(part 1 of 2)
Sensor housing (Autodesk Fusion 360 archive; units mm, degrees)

design "Attacco Sensori Def 4" references "Connettore Sensori"
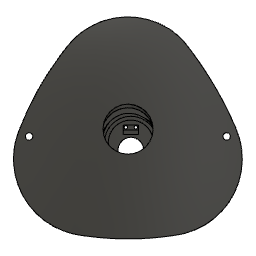
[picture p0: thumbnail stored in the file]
component_insert "Inserimento componente"
work_plane "Piano di lavoro1" AlongDistance 0
sketch "Schizzo1" plane through (0, 0, -8) normal (0, 0, 1) x axis (-1, 0, 0)
  line L1 (7.8557, -0.25) -> (4.1443, -6.6782)
  line L2 (4.1443, 6.6782) -> (7.8557, 0.25)
  line L3 (-3.7113, 6.9282) -> (3.7113, 6.9282)
  line L4 (-7.8557, 0.25) -> (-4.1443, 6.6782)
  line L5 (-4.1443, -6.6782) -> (-7.8557, -0.25)
  line L6 (3.7113, -6.9282) -> (-3.7113, -6.9282)
  curve K1
  circle C1 centre (0, 0) radius 5.5
  arc A1 centre (3.7113, -6.4282) radius 0.5 clockwise from (4.1443, -6.6782) to (3.7113, -6.9282)
  arc A2 centre (7.4226, 0) radius 0.5 clockwise from (7.8557, 0.25) to (7.8557, -0.25)
  arc A3 centre (3.7113, 6.4282) radius 0.5 clockwise from (3.7113, 6.9282) to (4.1443, 6.6782)
  arc A4 centre (-3.7113, 6.4282) radius 0.5 clockwise from (-4.1443, 6.6782) to (-3.7113, 6.9282)
  arc A5 centre (-7.4226, 0) radius 0.5 clockwise from (-7.8557, -0.25) to (-7.8557, 0.25)
  arc A6 centre (-3.7113, -6.4282) radius 0.5 clockwise from (-3.7113, -6.9282) to (-4.1443, -6.6782)
  circle C2 centre (0, 0) radius 6.9282
  circle C3 centre (0, 0) radius 5.5
  point P1 (0, 0)
  point P21 (0, 0)
  coincident P1 P21
  tangent L6 C2
extrude "Estrusione1" new body sketch "Schizzo1" profile of C1 C2 C3 along normal blind 26 bodies "Parte metallica"
extrude "Estrusione1" new body of existing geometry blind 29
sketch "Schizzo2" plane through (0, 0, 47) normal (0, 0, 1) x axis (-1, 0, 0)
  circle C1 centre (0, 0) radius 5.5
  circle C2 centre (0, 0) radius 6.9282
  circle C3 centre (0, 0) radius 6.9282
extrude "Estrusione2" add sketch "Schizzo2" against normal blind 2
sketch "Schizzo1" plane through (0, 0, 0) normal (0, 1, 0) x axis (1, 0, 0)
  line L1 (0, -20) -> (0, 20)
  line L2 (45.8258, 0) -> (0, 20)
  line L3 (0, -20) -> (45.8258, 0)
  line L4 (45.8258, 0) -> (0, 0)
  curve K1 (0, -17) -> (0, 0)
  curve K2 (6.8983, -16.9893) -> (0, -17)
  curve K3 (43.5589, -0.9893) -> (6.8983, -16.9893)
  curve K4 (43.5589, 0.9893) -> (43.5589, -0.9893)
  curve K5 (6.8983, 16.9893) -> (43.5589, 0.9893)
  curve K6 (0, 17) -> (6.8983, 16.9893)
  curve K7 (0, 0) -> (0, 17)
  curve K8 (0, 0) -> (0, 0)
  line L5 (0, -17) -> (0, 0)
  line L6 (0, 17) -> (0, 0)
  point P6 (0, 0)
  point P4 (0, 0)
  point P7 (0, -17)
  point P8 (6.8983, -16.9893)
  point P9 (43.5589, -0.9893)
  point P10 (43.5589, 0.9893)
  point P11 (6.8983, 16.9893)
  point P14 (0, 0)
  point P15 (0, -17)
  point P12 (0, 17)
  point P16 (0, 17)
  point P2 (0, -20)
  point P3 (0, 20)
  point P5 (45.8258, 0)
  midpoint L1 P6
  vertical L1
  horizontal L4
  coincident P4 P6
  coincident L1 P7
  coincident L3 P8
  coincident L3 P9
  coincident L2 P10
  coincident L2 P11
  coincident P4 P14
  coincident P7 P15
  coincident P12 P16
  perpendicular L4 L6
  vertical K4
  dimension "d2_1" distance P2 P3 = 40
  dimension "d7_1" distance P2 P5 = 50
  dimension "d8_1" distance P6 P16 = 17
  dimension "d9_1" distance P14 P15 = 17
  dimension "d10" distance P10 P11 = 40
  dimension "d11" distance P8 P9 = 40
  dimension "d18" = -1.5
extrude "Estrusione1" new body sketch "Schizzo1" profile of L4 K8 along normal blind 150 named "d3_1"
extrude "Estrusione3" add sketch "Schizzo1" profile of L4 along normal blind 1.5
fillet "Raccordo3" radius 5
sketch "Schizzo2" plane through (0, 0, 0) normal (1, 0, 0) x axis (0, 0, -1)
  line L1 (0.75, 138) -> (0.75, 136)
  line L2 (-0.75, 136) -> (-0.75, 138)
  line L3 (0, 138) -> (0, 136)
  line L4 (0, 137) -> (0, 0)
  arc A1 centre (0, 138) radius 0.75 clockwise from (-0.75, 138) to (0.75, 138)
  arc A2 centre (0, 136) radius 0.75 clockwise from (0.75, 136) to (-0.75, 136)
  point P8 (0, 137)
  point P1 (0, 0)
  point P9 (0, 0)
  point P10 (0, 137)
  point P6 (0, 136)
  point P7 (0, 138)
  tangent L1 A1
  tangent A1 L2
  parallel L1 L2
  tangent L2 A2
  tangent L1 A2
  vertical L3
  midpoint L3 P8
  coincident P1 P9
  vertical L4
  coincident P8 P10
  dimension "d23" distance L1 L2 = 1.5
  dimension "d24" distance P6 P7 = 2
  dimension "d59" distance P9 P10 = 137 (= "142.000002116 mm - 5 mm")
extrude "Estrusione4" cut sketch "Schizzo2" profile of L1 A1 L2 A2 to an object
path_pattern "SerieTraiettoria1" PathPatternDelta 34.6978
mirror "Specchio1" mirrorStitchTolerance 0.1
sketch "Schizzo3" plane through (0, 0, 0) normal (1, 0, 0) x axis (0, 0, -1)
  line L1 (-4.25, 134) -> (-4.25, 132)
  line L2 (-5.75, 132) -> (-5.75, 134)
  line L3 (-5, 134) -> (-5, 132)
  line L4 (-5, 0) -> (-5, 133)
  line L5 (0, 0) -> (-5, 0)
  arc A1 centre (-5, 134) radius 0.75 clockwise from (-5.75, 134) to (-4.25, 134)
  arc A2 centre (-5, 132) radius 0.75 clockwise from (-4.25, 132) to (-5.75, 132)
  point P8 (-5, 133)
  point P9 (-5, 133)
  point P1 (0, 0)
  point P11 (0, 0)
  point P6 (-5, 132)
  point P7 (-5, 134)
  point P10 (-5, 0)
  tangent L1 A1
  tangent A1 L2
  parallel L1 L2
  tangent L2 A2
  tangent L1 A2
  vertical L3
  midpoint L3 P8
  coincident P8 P9
  parallel L3 L4
  coincident P1 P11
  perpendicular L4 L5
  dimension "d32" distance L1 L2 = 1.5
  dimension "d33" distance P6 P7 = 2
  dimension "d60" distance P9 P10 = 133 (= "138.0000020564 mm - 5 mm")
extrude "Estrusione5" cut sketch "Schizzo3" profile of L1 A1 L2 A2 along normal blind 2
path_pattern "SerieTraiettoria2" PathPatternDelta 25.1145
mirror "Specchio2" mirrorStitchTolerance 0.1
rectangular_pattern "Serie R" countU 18 uSpaceDistance -100 vSpaceDistance 0
chamfer "Smusso1" distance 3 distance 2
sketch "Schizzo4" plane through (0, 150, 0) normal (0, 1, 0) x axis (-1, 0, 0)
  line L1 (0, 0) -> (-42.5, 0)
  point P1 (0, 0)
  point P3 (0, 0)
  coincident P1 P3
  horizontal L1
work_plane "Piano di lavoro1" sketch "Schizzo4" AlongDistance 30
sketch "Schizzo5" plane through (17.7061, 180, 0) normal (0, 1, 0) x axis (1, 0, 0)
  curve K1 (-14.1843, -11.4353) -> (-14.1843, 0)
  curve K2 (-4, -14) -> (-14.1843, -11.4353)
  curve K3 (23.2456, -1.1467) -> (-4, -14)
  curve K4 (23.2456, 1.1467) -> (23.2456, -1.1467)
  curve K5 (-4, 14) -> (23.2456, 1.1467)
  curve K6 (-14.1843, 11.8868) -> (-4, 14)
  curve K7 (-14.1843, 0) -> (-14.1843, 11.8868)
  curve K8 (-14.1843, 0) -> (-14.1843, 0)
  point P8 (-14.1843, 11.8868)
  point P2 (-14.1843, 0)
  point P9 (-14.1843, 0)
  coincident P8
  coincident P2 P9
  parallel K1 K7
sketch "Schizzo6" plane through (0, 0, 0) normal (0, 0, 1) x axis (1, 0, 0)
  curve K1 (0.0014, 160.046) -> (0, 150)
  curve K2 (3.5218, 160.5734) -> (0.0014, 160.046)
  curve K3 (3.5218, 180) -> (3.5218, 160.5734)
  curve K4 (3.5218, 180) -> (0, 150)
  line L1 (13.7061, 180) -> (3.5218, 180)
  line L2 (33.5076, 150) -> (33.4619, 180)
  point P2 (3.5218, 180)
  point P8 (3.5218, 180)
  point P3 (33.4619, 180)
  point P11 (33.4619, 180)
  coincident P2 P8
  perpendicular K3 L1
  coincident P3 P11
work_plane "Piano di lavoro2" AlongDistance 17
sketch "Schizzo7" plane through (17, 0, 0) normal (1, 0, 0) x axis (0, 0, -1)
  curve K1 (-11.9, 160.0016) -> (-11.7395, 150)
  curve K2 (-9.8125, 160.0015) -> (-11.9, 160.0016)
  curve K3 (-10.1921, 180) -> (-9.8125, 160.0015)
  curve K4 (-10.1921, 180) -> (-11.7395, 150)
  curve K5 (11.9001, 160.0043) -> (11.7395, 150)
  curve K6 (9.6921, 160.004) -> (11.9001, 160.0043)
  curve K7 (10.3156, 180) -> (9.6921, 160.004)
  curve K8 (10.3156, 180) -> (11.7395, 150)
  point P4 (-11.7395, 150)
  point P6 (-11.7395, 150)
  point P2 (-10.1921, 180)
  point P9 (-10.1921, 180)
  point P5 (11.7395, 150)
  point P10 (11.7395, 150)
  point P3 (10.3156, 180)
  point P13 (10.3156, 180)
  coincident P4 P6
  coincident P2 P9
  coincident P5 P10
  coincident P3 P13
loft "Loft1"
sketch "Schizzo10" plane through (0, 0, 0) normal (1, 0, 0) x axis (0, 0, -1)
thicken "Ispessisci1" Thickness -1.5
sketch "Schizzo9" plane through (0, 150, 0) normal (0, 1, 0) x axis (-1, 0, 0)
  dimension "d52" distance = -0.75 (= "( -1.5 / 2 ) * 1 mm")
  dimension "d53" distance = -0.7
  dimension "d54" distance = -0.8
extrude "Estrusione6" cut sketch "Schizzo9" against normal blind 3
extrude "Estrusione7" add sketch "Schizzo9" against normal blind 3
sketch "Schizzo11" plane through (0, 0, 0) normal (0, 0, 1) x axis (1, 0, 0)
component_from_bodies "Corpo->Comp1"
remove_body "RimuoviCorpo2"
remove_body "RimuoviCorpo3"
move "Sposta1"
work_plane "Piano di lavoro3" AlongDistance 142
work_plane "Piano di lavoro4" AlongDistance 17
split "Dividi1"
split "Dividi2"
split "Dividi3"
sketch "Schizzo8" plane through (0, 150, 0) normal (0, 1, 0) x axis (-1, 0, 0)
  curve K1 (-30.2634, -0.0045) -> (-3.25, 0)
  curve K2 (-3.25, 0) -> (-30.2634, -0.0045)
  dimension "d50" distance = 0.15
  dimension "d51" distance = 1.75
extrude "Estrusione2" new body sketch "Schizzo1" profile of L1 L2 L3 L4 K8 L5 L6 along normal blind 150
fillet "Raccordo2" radius 5 5
position "Posizione1"
sketch "Schizzo3" plane through (0, 0, -13) normal (0, 0, -1) x axis (1, 0, 0)
position "Posizione2"
work_plane "Piano di lavoro3" AlongDistance -3
sketch "Schizzo11" plane through (0, 0, -13) normal (0, 0, -1) x axis (1, 0, 0)
  line L1 (3.7113, -6.9282) -> (-3.7113, -6.9282)
  line L2 (7.8557, -0.25) -> (4.1443, -6.6782)
  line L3 (4.1443, 6.6782) -> (7.8557, 0.25)
  line L4 (-3.7113, 6.9282) -> (3.7113, 6.9282)
  line L5 (-7.8557, 0.25) -> (-4.1443, 6.6782)
  line L6 (-4.1443, -6.6782) -> (-7.8557, -0.25)
  curve K1 (22.6866, -2.0856) -> (22.692, 2.0722)
  curve K2 (3.052, -14.4876) -> (22.6866, -2.0856)
  curve K3 (-14.4061, 0) -> (3.052, -14.4876)
  curve K4 (3.1244, 14.4607) -> (-14.4061, 0)
  curve K5 (22.692, 2.0722) -> (3.1244, 14.4607)
  arc A1 centre (-3.7113, -6.4282) radius 0.5 clockwise from (-3.7113, -6.9282) to (-4.1443, -6.6782)
  arc A2 centre (3.7113, -6.4282) radius 0.5 clockwise from (4.1443, -6.6782) to (3.7113, -6.9282)
  arc A3 centre (7.4226, 0) radius 0.5 clockwise from (7.8557, 0.25) to (7.8557, -0.25)
  arc A4 centre (3.7113, 6.4282) radius 0.5 clockwise from (3.7113, 6.9282) to (4.1443, 6.6782)
  arc A5 centre (-3.7113, 6.4282) radius 0.5 clockwise from (-4.1443, 6.6782) to (-3.7113, 6.9282)
  arc A6 centre (-7.4226, 0) radius 0.5 clockwise from (-7.8557, -0.25) to (-7.8557, 0.25)
  circle C1 centre (0, 0) radius 5.5
work_plane "Piano di lavoro4" AlongDistance -3
sketch "Schizzo13" plane through (4.3286, 0, -43) normal (0, 0, -1) x axis (1, 0, 0)
  curve K1 (-1.874, 12.5865) -> (-16.7061, 0)
  curve K2 (16.5346, 1.3304) -> (-1.874, 12.5865)
  curve K3 (-16.7061, 0) -> (-1.9443, -12.6127)
  curve K4 (-1.9443, -12.6127) -> (16.531, -1.3396)
  curve K5 (16.531, -1.3396) -> (16.5346, 1.3304)
  curve K6 (18.3866, -2.0856) -> (18.392, 2.0722)
  curve K7 (-1.248, -14.4876) -> (18.3866, -2.0856)
  curve K8 (-18.7061, 0) -> (-1.248, -14.4876)
  curve K9 (-1.1756, 14.4607) -> (-18.7061, 0)
  curve K10 (18.392, 2.0722) -> (-1.1756, 14.4607)
  dimension "d220" = -2
sketch "Schizzo14" plane through (0, 0, 0) normal (0, 1, 0) x axis (1, 0, 0)
  line L1 (21.0845, 13) -> (-8.8557, 13)
  line L2 (21.1301, 43) -> (20.8596, 43)
  line L3 (21.0845, 13) -> (21.1301, 43)
  line L4 (22.1301, 42.9985) -> (21.1301, 43)
  line L5 (21.0845, 13) -> (23.121, 43)
  point P5 (21.1301, 43)
  point P6 (21.1301, 43)
  point P3 (21.0845, 13)
  point P7 (21.0845, 13)
  point P9 (23.121, 43)
  point P10 (23.121, 43)
  point P8 (22.1301, 42.9985)
  coincident P5 P6
  coincident P3 P7
  perpendicular L3 L4
  coincident P9 P10
  dimension "d223" distance P6 P8 = 1
sketch "Schizzo47" plane through (0, 0, 0) normal (0, 1, 0) x axis (1, 0, 0)
  curve K1 (-14.0983, 33.0239) -> (-14.3774, 43)
  curve K2 (-9, 25) -> (-14.0983, 33.0239)
  curve K3 (-8.8557, 13) -> (-9, 25)
  curve K4 (-8.8557, 13) -> (-14.3774, 43)
  point P2 (-14.3774, 43)
  point P3 (-14.3774, 43)
  coincident P2 P3
loft "Loft1" sketch "Schizzo11" + "Schizzo13"
component_from_bodies "Corpo->Comp1"
sketch "Schizzo15" plane through (0, 0, -13) normal (0, 0, 1) x axis (-1, 0, 0)
  line L1 (-21.1554, -0.0082) -> (1, -0.0082)
  line L2 (-9, 2.9918) -> (-7, 2.9918)
  line L3 (-9, -3.0082) -> (-9, 2.9918)
  line L4 (-7, -3.0082) -> (-9, -3.0082)
  line L5 (-7, 2.9918) -> (-7, -3.0082)
  line L6 (-9, -3.0082) -> (-7, 2.9918)
  line L7 (-7, -3.0082) -> (-9, 2.9918)
  curve K1 (-3.1244, 14.4607) -> (14.4061, 0)
  curve K2 (-22.692, 2.0722) -> (-3.1244, 14.4607)
  curve K3 (-22.6866, -2.0856) -> (-22.692, 2.0722)
  curve K4 (-3.052, -14.4876) -> (-22.6866, -2.0856)
  curve K5 (14.4061, 0) -> (-3.052, -14.4876)
  circle C1 centre (1, -0.0082) radius 5.7
  circle C2 centre (1, -0.0082) radius 10.7
  circle C3 centre (-8.1307, -2.0039) radius 0.7
  circle C4 centre (-8.1307, 1.9875) radius 0.7
  point P10 (-8, -0.0082)
  point P3 (1, -0.0082)
  point P2 (1, -0.0082)
  point P4 (1, -0.0082)
  point P8 (-9, -3.0082)
  point P9 (-7, -3.0082)
  point P7 (-9, 2.9918)
  point P11 (-8.1307, -2.0039)
  point P1 (0, 0)
  horizontal L1
  horizontal L2
  perpendicular L2 L3
  parallel L2 L4
  parallel L3 L5
  coincident L6 P10
  coincident L7 P10
  coincident L1 P10
  symmetric L1 C3 C4
  coincident P3 L1
  coincident P2 P4
  coincident P2 P3
  dimension "d76" diameter C1 = 11.4
  dimension "d77" diameter C2 = 21.4
  dimension "d78" distance P8 P9 = 2
  dimension "d79" distance P7 P8 = 6
  dimension "d80" distance P3 P10 = 9
  dimension "d81" diameter C3 = 1.4
  dimension "d82" distance P10 P11 = 2
  dimension "d217" distance P1 P3 = 1
extrude "Estrusione1" cut sketch "Schizzo15" profile of C1 C3 C4 no distance stored
move "Sposta1"
move "Sposta2"
position "Posizione4"
sketch "Schizzo16" plane through (0, 0, -43) normal (0, 0, -1) x axis (1, 0, 0)
  line L1 (2, 0) -> (0, 0)
  curve K1 (3.153, 14.4607) -> (-14.3774, 0)
  curve K2 (-14.3774, 0) -> (3.0806, -14.4876)
  curve K3 (3.0806, -14.4876) -> (22.7152, -2.0856)
  curve K4 (22.7152, -2.0856) -> (22.7206, 2.0722)
  curve K5 (22.7206, 2.0722) -> (3.153, 14.4607)
  circle C1 centre (2, 0) radius 9
  circle C2 centre (8.1307, -2.0039) radius 0.7
  point P1 (0, 0)
  point P3 (0, 0)
  point P2 (2, 0)
  point P4 (2, 0)
  coincident P1 P3
  coincident P2 P4
  horizontal L1
  dimension "d218" diameter C1 = 18
  dimension "d219" distance P3 P4 = 2
extrude "Estrusione2" cut sketch "Schizzo16" profile of C1 against normal blind 10
sketch "Schizzo19" plane through (0, 0, -33) normal (0, 0, -1) x axis (1, 0, 0)
  line L1 (9, -3.0082) -> (9, 2.9918)
  line L2 (7, -3.0082) -> (9, -3.0082)
  line L3 (7, 2.9918) -> (7, -3.0082)
  line L4 (9, 2.9918) -> (7, 2.9918)
  circle C1 centre (-1, -0.0082) radius 5.7
  circle C2 centre (8.1307, -2.0039) radius 0.7
  circle C3 centre (8.1307, 1.9875) radius 0.7
  circle C4 centre (2, 0) radius 9
extrude "Estrusione3" cut sketch "Schizzo19" profile of C2 L1 L2 L3 L4 against normal blind 18
sketch "Schizzo20" plane through (0, 0, -33) normal (0, 0, -1) x axis (1, 0, 0)
  line L1 (6, 1.5079) -> (7, 1.5079)
  line L2 (6, -1.5083) -> (6, 1.5079)
  line L3 (7, -1.5083) -> (6, -1.5083)
  line L4 (7, 1.5079) -> (7, -1.5083)
  line L5 (7, -3.0082) -> (9, -3.0082)
  line L6 (7, 2.9918) -> (7, -3.0082)
  line L7 (9, 2.9918) -> (7, 2.9918)
  line L8 (9, -3.0082) -> (9, 2.9918)
  circle C1 centre (-1, -0.0082) radius 5.7
  circle C2 centre (2, 0) radius 9
  point P2 (7, 1.5079)
  point P3 (6, 1.5079)
  horizontal L1
  vertical L2
  horizontal L3
  vertical L4
  coincident P2 L6
  dimension "d90" distance P2 P3 = 1
extrude "Estrusione4" cut sketch "Schizzo20" profile of L1 L2 L3 L4 against normal blind 4.5
sketch "Schizzo21" plane through (0, 0, -43) normal (0, 0, -1) x axis (1, 0, 0)
  curve K1 (3.153, 14.4607) -> (-14.3774, 0)
  curve K2 (-14.3774, 0) -> (3.0806, -14.4876)
  curve K3 (3.0806, -14.4876) -> (22.7152, -2.0856)
  curve K4 (22.7152, -2.0856) -> (22.7206, 2.0722)
  curve K5 (22.7206, 2.0722) -> (3.153, 14.4607)
  circle C1 centre (2, 0) radius 12.2
  circle C2 centre (2, 0) radius 9
  circle C3 centre (2, 0) radius 12.25
  circle C4 centre (2, 0) radius 10.5
  circle C5 centre (2, 0) radius 9
  point P2 (2, 0)
  point P3 (2, 0)
  point P4 (2, 0)
  coincident P2 P3
  coincident P2 P4
  dimension "d138" diameter C1 = 24.4
  dimension "d214" diameter C3 = 24.5
  dimension "d215" diameter C4 = 21
  dimension "d216" diameter C2 = 18
extrude "Estrusione5" new body sketch "Schizzo21" profile of C2 C4 along normal blind 4
sketch "Schizzo22" plane through (0, 0, -13) normal (0, 0, 1) x axis (-1, 0, 0)
  circle C1 centre (1.1608, 0) radius 5.5
  circle C2 centre (1, 0) radius 4.5
  circle C3 centre (1, 0) radius 4.5
  dimension "d97" diameter C1 = 11
extrude "Estrusione6" cut sketch "Schizzo22" profile of C1 against normal blind 10
component_from_bodies "Corpo->Comp2"
chamfer "Smusso2" distance 0.3
chamfer "Smusso4" distance 0.5
thread "Filettatura1" ThreadOffset 2 ThreadLength 2
offset_faces "FacceDiOffset1" distance -0.1
offset_faces "FacceDiOffset2" distance -0.1
thread "Filettatura2" ThreadOffset 12 ThreadLength 8
sketch "Schizzo80" plane through (0, 0, 0) normal (0, 1, 0) x axis (1, 0, 0)
offset_faces "FacceDiOffset3" distance -0.1
offset_faces "FacceDiOffset4" distance -0.1
sketch "Schizzo23" plane through (0, 0, -33) normal (0, 0, -1) x axis (1, 0, 0)
  line L1 (9, 2.9918) -> (7, 2.9918)
  line L2 (9, -3.0082) -> (9, 2.9918)
  line L3 (7, -3.0082) -> (9, -3.0082)
  line L4 (7, 2.9918) -> (7, 1.5079)
  line L5 (7, -3.0082) -> (7, 2.9918)
  line L6 (9, -3.0082) -> (7, -3.0082)
  line L7 (9, 2.9918) -> (9, -3.0082)
  line L8 (7, 2.9918) -> (9, 2.9918)
  line L9 (5.2, 2.9918) -> (9, 2.9918)
  line L10 (5.2, -3.0082) -> (5.2, 2.9918)
  line L11 (9, -3.0082) -> (5.2, -3.0082)
  line L12 (9, 2.9918) -> (9, -3.0082)
  line L13 (6, -1.5083) -> (7, -1.5083)
  line L14 (6, 1.5079) -> (6, -1.5083)
  line L15 (7, 1.5079) -> (6, 1.5079)
  line L16 (7, -1.5083) -> (7, -3.0082)
  circle C1 centre (-1, -0.0082) radius 5.1368
  circle C2 centre (8.1307, -2.0039) radius 0.7
  circle C3 centre (8.1307, 1.9875) radius 0.7
  circle C4 centre (2, 0) radius 9
  point P10 (9, 2.9918)
  point P11 (9, 2.9918)
  point P12 (5.2, 2.9918)
  horizontal L9
  vertical L10
  horizontal L11
  vertical L12
  coincident P10 P11
  dimension "d110" distance P11 P12 = 3.8
extrude "Estrusione7" cut sketch "Schizzo23" profile of L1 L2 L3 L4 L5 L6 L7 L8 L9 L10 L11 L12 against normal blind 8
sketch "Schizzo24" plane through (0, 0, -43) normal (0, 0, -1) x axis (1, 0, 0)
  line L1 (-11.5616, 0) -> (-12.3774, 0)
  curve K1 (2.5584, -13.0814) -> (21.3235, -1.5261)
  curve K2 (-12.8774, 0) -> (2.5584, -13.0814)
  curve K3 (2.6292, 13.0551) -> (-12.8774, 0)
  curve K4 (21.3276, 1.5159) -> (2.6292, 13.0551)
  curve K5 (21.3235, -1.5261) -> (21.3276, 1.5159)
  curve K6 (3.153, 14.4607) -> (-14.3774, 0)
  curve K7 (-14.3774, 0) -> (3.0806, -14.4876)
  curve K8 (3.0806, -14.4876) -> (22.7152, -2.0856)
  curve K9 (22.7152, -2.0856) -> (22.7206, 2.0722)
  curve K10 (22.7206, 2.0722) -> (3.153, 14.4607)
  circle C1 centre (2, 0) radius 9
extrude "Estrusione1" new body sketch "Schizzo24" profile of K1 K2 K3 K5 K4 along normal blind 100
sketch "Schizzo46" plane through (0, 0, -43) normal (0, 0, -1) x axis (1, 0, 0)
  curve K1 (3.153, 14.4607) -> (-14.3774, 0)
  curve K2 (-14.3774, 0) -> (3.0806, -14.4876)
  curve K3 (3.0806, -14.4876) -> (22.7152, -2.0856)
  curve K4 (22.7152, -2.0856) -> (22.7206, 2.0722)
  curve K5 (22.7206, 2.0722) -> (3.153, 14.4607)
  circle C1 centre (2, 0) radius 9
  circle C2 centre (2, 0) radius 9
  circle C3 centre (2, 0) radius 12
  circle C4 centre (2, 0) radius 9
  concentric C1 C3
  dimension "d227" diameter C3 = 24
sketch "Schizzo29" plane through (0, 0, -143) normal (0, 0, -1) x axis (1, 0, 0)
  curve K1 (17.6987, -12.6127) -> (2.9418, -0.9798)
  curve K2 (36.174, -1.3396) -> (17.6987, -12.6127)
  curve K3 (36.1777, 1.3304) -> (36.174, -1.3396)
  curve K4 (17.769, 12.5865) -> (36.1777, 1.3304)
  curve K5 (2.9418, 0.9798) -> (17.769, 12.5865)
  line L1 (2.9418, -0.9798) -> (2.9418, 0.9798)
  curve K6 (21.3276, 1.5159) -> (2.6292, 13.0551)
  curve K7 (21.3235, -1.5261) -> (21.3276, 1.5159)
  curve K8 (2.5584, -13.0814) -> (21.3235, -1.5261)
  curve K9 (-12.8774, 0) -> (2.5584, -13.0814)
  curve K10 (2.6292, 13.0551) -> (-12.8774, 0)
  curve K11 (-14.3774, 0) -> (3.153, 14.4607)
  curve K12 (3.0806, -14.4876) -> (-14.3774, 0)
  curve K13 (22.7152, -2.0856) -> (3.0806, -14.4876)
  curve K14 (22.7206, 2.0722) -> (22.7152, -2.0856)
  curve K15 (3.153, 14.4607) -> (22.7206, 2.0722)
extrude "Estrusione7" add sketch "Schizzo46" profile of C3 along normal blind 4
thread "Filettatura2" ThreadOffset 2 ThreadLength 2
sketch "Schizzo48" plane through (0, 0, -43) normal (0, 0, -1) x axis (1, 0, 0)
  curve K1 (3.153, 14.4607) -> (-14.3774, 0)
  curve K2 (-14.3774, 0) -> (3.0806, -14.4876)
  curve K3 (3.0806, -14.4876) -> (22.7152, -2.0856)
  curve K4 (22.7152, -2.0856) -> (22.7206, 2.0722)
  curve K5 (22.7206, 2.0722) -> (3.153, 14.4607)
  circle C1 centre (2, 0) radius 9
  circle C2 centre (2, 0) radius 9
  circle C3 centre (2, 0) radius 10.5
  circle C4 centre (2, 0) radius 12.1
  circle C5 centre (2, 0) radius 9
  concentric C1 C3
  dimension "d231" = 3.1
extrude "Estrusione8" cut sketch "Schizzo48" profile of C3 C4 blind 4 from offset 2
work_plane "Piano di lavoro6" AlongDistance 0
work_plane "Piano di lavoro7" AlongDistance 20
sketch "Schizzo33" plane through (0, 0, -43) normal (0, 0, -1) x axis (1, 0, 0)
  curve K1 (2.5943, 12.9614) -> (-12.7726, 0.9788)
  curve K2 (21.2347, 1.4788) -> (2.5943, 12.9614)
  curve K3 (21.2307, -1.4888) -> (21.2347, 1.4788)
  curve K4 (2.5236, -12.9877) -> (21.2307, -1.4888)
  curve K5 (-12.7726, -0.9788) -> (2.5236, -12.9877)
  line L1 (-12.7726, 0.9788) -> (-12.7726, -0.9788)
  line L2 (-10.2726, 0.9662) -> (-10.2726, -0.9662)
  curve K6 (1.7213, 10.6187) -> (-10.2726, 0.9662)
  curve K7 (18.913, 0.5516) -> (1.7213, 10.6187)
  curve K8 (18.9112, -0.5562) -> (18.913, 0.5516)
  curve K9 (1.6533, -10.6441) -> (18.9112, -0.5562)
  curve K10 (-10.2726, -0.9662) -> (1.6533, -10.6441)
  curve K11 (3.153, 14.4607) -> (-14.3774, 0)
  curve K12 (-14.3774, 0) -> (3.0806, -14.4876)
  curve K13 (3.0806, -14.4876) -> (22.7152, -2.0856)
  curve K14 (22.7152, -2.0856) -> (22.7206, 2.0722)
  curve K15 (22.7206, 2.0722) -> (3.153, 14.4607)
  circle C1 centre (2, 0) radius 9
  dimension "d196" = 2.5
extrude "Estrusione1" new body sketch "Schizzo33" profile of K2 K1 K3 K4 K5 L1 K10 L2 K9 K6 K7 K8 along normal blind 100
sketch "Schizzo50" plane through (0, 0, -47) normal (0, 0, -1) x axis (1, 0, 0)
  curve K1 (2.6292, 13.0551) -> (-12.8774, 0)
  curve K2 (-12.8774, 0) -> (2.5584, -13.0814)
  curve K3 (2.5584, -13.0814) -> (21.3235, -1.5261)
  curve K4 (21.3235, -1.5261) -> (21.3276, 1.5159)
  curve K5 (21.3276, 1.5159) -> (2.6292, 13.0551)
  curve K6 (21.3276, 1.5159) -> (2.6292, 13.0551)
  curve K7 (21.3235, -1.5261) -> (21.3276, 1.5159)
  curve K8 (2.5584, -13.0814) -> (21.3235, -1.5261)
  curve K9 (-12.8774, 0) -> (2.5584, -13.0814)
  curve K10 (2.6292, 13.0551) -> (-12.8774, 0)
  curve K11 (-14.3774, 0) -> (3.153, 14.4607)
  curve K12 (3.0806, -14.4876) -> (-14.3774, 0)
  curve K13 (22.7152, -2.0856) -> (3.0806, -14.4876)
  curve K14 (22.7206, 2.0722) -> (22.7152, -2.0856)
  curve K15 (3.153, 14.4607) -> (22.7206, 2.0722)
  curve K16 (20.8633, 1.3304) -> (2.4546, 12.5865)
  curve K17 (20.8596, -1.3396) -> (20.8633, 1.3304)
  curve K18 (2.3843, -12.6127) -> (20.8596, -1.3396)
  curve K19 (-12.3774, 0) -> (2.3843, -12.6127)
  curve K20 (2.4546, 12.5865) -> (-12.3774, 0)
  circle C1 centre (2, 0) radius 12.1
  dimension "d239" = 0.5
work_plane "Piano di lavoro8" AlongDistance 20
sketch "Schizzo34" plane through (4.426, -0.041, -163) normal (0, 0, -1) x axis (1, 0, 0)
  circle C1 centre (0, 0) radius 25
  circle C2 centre (0, 0) radius 22.5
  point P1 (0, 0)
  point P2 (0, 0)
  coincident P1 P2
  dimension "d159" diameter C1 = 50
  dimension "d197" = -2.5
sketch "Schizzo40" plane through (0, 0, -143) normal (0, 0, -1) x axis (1, 0, 0)
  curve K1 (1.6533, -10.6441) -> (18.9112, -0.5562)
  curve K2 (-10.2726, -0.9662) -> (1.6533, -10.6441)
  line L1 (-10.2726, 0.9662) -> (-10.2726, -0.9662)
  curve K3 (1.7213, 10.6187) -> (-10.2726, 0.9662)
  curve K4 (18.913, 0.5516) -> (1.7213, 10.6187)
  curve K5 (18.9112, -0.5562) -> (18.913, 0.5516)
  curve K6 (2.5236, -12.9877) -> (-12.7726, -0.9788)
  curve K7 (21.2307, -1.4888) -> (2.5236, -12.9877)
  curve K8 (21.2347, 1.4788) -> (21.2307, -1.4888)
  curve K9 (2.5943, 12.9614) -> (21.2347, 1.4788)
  curve K10 (-12.7726, 0.9788) -> (2.5943, 12.9614)
  line L2 (-12.7726, -0.9788) -> (-12.7726, 0.9788)
  curve K11 (-14.3774, 0) -> (3.153, 14.4607)
  curve K12 (3.0806, -14.4876) -> (-14.3774, 0)
  curve K13 (22.7152, -2.0856) -> (3.0806, -14.4876)
  curve K14 (22.7206, 2.0722) -> (22.7152, -2.0856)
  curve K15 (3.153, 14.4607) -> (22.7206, 2.0722)
  curve K16 (21.3276, 1.5159) -> (2.6292, 13.0551)
  curve K17 (21.3235, -1.5261) -> (21.3276, 1.5159)
  curve K18 (2.5584, -13.0814) -> (21.3235, -1.5261)
  curve K19 (-12.8774, 0) -> (2.5584, -13.0814)
  curve K20 (2.6292, 13.0551) -> (-12.8774, 0)
work_plane "Piano di lavoro10" AlongDistance -168 (= "-173.00 mm + 5 mm")
sketch "Schizzo42" plane through (0, 0, -168) normal (0, 0, 1) x axis (1, 0, 0)
  circle C1 centre (4.426, -0.041) radius 25
  circle C2 centre (4.426, -0.041) radius 25
  concentric C1 C2
sketch "Schizzo43" plane through (0, 0, 0) normal (0, 1, 0) x axis (1, 0, 0)
  line L1 (-12.7726, 43) -> (-12.7726, 143)
  line L2 (21.5261, 143) -> (21.5261, 43)
  curve K1 (-21, 165) -> (-20.574, 168)
  curve K2 (-14.5, 165) -> (-21, 165)
  curve K3 (-14.3774, 143) -> (-14.5, 165)
  curve K4 (-14.3774, 143) -> (-20.574, 168)
  curve K5 (29.5, 165) -> (29.426, 168)
  curve K6 (23, 165) -> (29.5, 165)
  curve K7 (23.121, 143) -> (23, 165)
  curve K8 (23.121, 143) -> (29.426, 168)
  point P3 (-20.574, 168)
  point P8 (-20.574, 168)
  point P2 (29.426, 168)
  point P11 (29.426, 168)
  point P15 (23.121, 143)
  point P16 (23.121, 143)
  point P14 (-14.3774, 143)
  point P17 (-14.3774, 143)
  coincident P3 P8
  coincident P2 P11
  coincident P15 P16
  coincident P14 P17
sketch "Schizzo44" plane through (0, 0, 0) normal (1, 0, 0) x axis (0, 0, -1)
  line L1 (143, -13.8593) -> (43, -13.8593)
  line L2 (43, 13.8638) -> (143, 13.8638)
  curve K1 (164.8154, 24.5237) -> (168, 24.5641)
  curve K2 (163, 16) -> (164.8154, 24.5237)
  curve K3 (143, 15.5374) -> (163, 16)
  curve K4 (143, 15.5374) -> (168, 24.5641)
  curve K5 (163, -15) -> (143, -15.534)
  curve K6 (165.2357, -24.6461) -> (163, -15)
  curve K7 (168, -24.6461) -> (165.2357, -24.6461)
  curve K8 (168, -24.6461) -> (143, -15.534)
  point P9 (168, 24.5641)
  point P10 (168, 24.5641)
  point P8 (168, -24.6461)
  point P15 (168, -24.6461)
  point P16 (143, -15.534)
  point P18 (143, -15.534)
  point P17 (143, 15.5374)
  point P19 (143, 15.5374)
  coincident P9 P10
  coincident P8 P15
  coincident P16 P18
  coincident P17 P19
loft "Loft3"
thicken "Ispessisci1" Thickness -1.5
copy_paste_bodies "TagliaIncollaCorpi"
sketch "Schizzo41" plane through (0, 0, 0) normal (0, 1, 0) x axis (1, 0, 0)
  line L1 (32, 169.5797) -> (-21, 169.5797)
  line L2 (32, 165.6356) -> (32, 169.5797)
  line L3 (-21, 165.6356) -> (32, 165.6356)
  line L4 (-21, 169.5797) -> (-21, 165.6356)
  line L5 (29.426, 168) -> (-20.574, 168)
  horizontal L1
  vertical L2
  horizontal L3
  vertical L4
extrude "Estrusione2" cut sketch "Schizzo41" profile of L1 L2 L3 L4 distance 39
work_plane "Piano di lavoro11" AlongDistance -155
sketch "Schizzo53" plane through (6.1528, 0.1078, -168) normal (0, 0, 1) x axis (1, 0, 0)
sketch "Schizzo35" plane through (4.426, -0.041, -168) normal (0, 0, 1) x axis (1, 0, 0)
  curve K1 (38.9637, 17.3095) -> (0.0757, 43.001)
  curve K2 (38.2093, -18.3657) -> (38.2094, -18.3657)
  line L1 (-44.3112, 45.6346) -> (44.3112, 45.6346)
  line L2 (-44.3112, -45.6346) -> (-44.3112, 45.6346)
  line L3 (44.3112, 45.6346) -> (-44.3112, -45.6346)
  line L4 (44.3112, 45.6346) -> (44.3112, -45.6346)
  curve K3 (-7.7461, -45.2786) -> (-2.1655, -43.6439)
  curve K4 (0.0757, 43.001) -> (38.9637, 17.3095)
  line L5 (44.3112, -45.6346) -> (-44.3112, -45.6346)
  line L6 (44.3112, -45.6346) -> (-44.3112, 45.6346)
  line L7 (-13.0565, -45.6346) -> (-13.0565, 45.6346)
  line L8 (25, -0.041) -> (23.5, -0.0385)
  line L9 (23.5, -0.0385) -> (25, -0.041)
  circle C1 centre (-3.3996, 39.4216) radius 1.5
  circle C2 centre (0, 0) radius 10
  circle C3 centre (-3.3996, -39.4216) radius 1.5
  circle C4 centre (0, 0) radius 25
position "Posizione5"
sketch "Schizzo54" plane through (6.1528, 0.1078, -168) normal (0, 0, 1) x axis (1, 0, 0)
  line L1 (23.2048, -0.09) -> (21.7053, -0.0925)
  line L2 (21.7053, -0.0925) -> (23.2048, -0.09)
  circle C1 centre (-1.7952, -0.131) radius 25
sketch "Schizzo55" plane through (0, 0, 0) normal (0, 1, 0) x axis (1, 0, 0)
  line L1 (20.7114, 13) -> (5.92, 13)
  line L2 (20.7114, 183) -> (20.7114, 13)
  point P3 (20.7114, 13)
  point P4 (20.7114, 13)
  point P5 (20.7114, 183)
  point P6 (29.3576, 168)
  coincident P3 P4
  perpendicular L1 L2
  dimension "d248" distance P4 P5 = 170
  dimension "d249" distance P5 P6 = 15
work_plane "Piano di lavoro12" AlongDistance -15
sketch "Schizzo51" plane through (0, 0, 0) normal (1, 0, 0) x axis (0, 1, 0)
sketch "Schizzo56" plane through (0, 0, -168) normal (0, 0, 1) x axis (1, 0, 0)
sketch "Schizzo57" plane through (6.1528, 0.1078, -183) normal (0, 0, 1) x axis (1, 0, 0)
  curve K1 (-1.6511, 42.8523) -> (37.2368, 17.1607)
  curve K2 (37.2368, 17.1607) -> (-1.6511, 42.8523)
  circle C1 centre (-5.1264, 39.2729) radius 1.5
  circle C2 centre (-5.1264, -39.5703) radius 1.5
sketch "Schizzo59" plane through (6.1528, 0.1078, -168) normal (0, 0, 1) x axis (1, 0, 0)
  line L1 (23.2048, -0.09) -> (21.7053, -0.0925)
  line L2 (21.7053, -0.0925) -> (23.2048, -0.09)
sketch "Schizzo70" plane through (0, 0, -165.5584) normal (0, 0, -1) x axis (1, 0, 0)
  curve K1 (25.2744, -0.0208) -> (25.2744, -0.0208)
  circle C1 centre (4, 0) radius 24.5
  dimension "d326" diameter C1 = 49
  dimension "d311" distance = -1
extrude "Estrusione10" add sketch "Schizzo70" along normal blind 15 and against normal blind 2
extrude "Estrusione4" add sketch "Schizzo57" along normal blind 3 and along normal blind 1
sketch "Schizzo36" plane through (-0.0683, 0.0177, -182) normal (0, 0, 1) x axis (1, 0, 0)
  curve K1 (43.1302, 17.1389) -> (42.3831, -18.0677)
  curve K2 (4.4169, 42.6902) -> (43.1302, 17.1389)
  curve K3 (42.3831, -18.0677) -> (4.4169, 42.6902)
  line L1 (42.3831, -18.0677) -> (42.3831, -18.0677)
  curve K4 (43.458, 17.2508) -> (4.57, 42.9423)
  curve K5 (4.57, 42.9423) -> (43.458, 17.2508)
  curve K6 (43.458, 17.2508) -> (4.57, 42.9423)
  curve K7 (4.57, 42.9423) -> (43.458, 17.2508)
  circle C1 centre (1.0947, 39.3629) radius 1.5
  circle C2 centre (1.0947, -39.4803) radius 1.5
  circle C3 centre (4.426, -0.041) radius 25
  circle C4 centre (1.0947, -39.4803) radius 1.5
  circle C5 centre (1.0947, 39.3629) radius 1.5
  circle C6 centre (4.426, -0.041) radius 25
extrude "Estrusione5" cut sketch "Schizzo36" profile of K3 K2 K1 L1 to an object
sketch "Schizzo45" plane through (-0.0683, 0.0177, -180) normal (0, 0, 1) x axis (1, 0, 0)
  curve K1 (21.4787, 1.0728) -> (21.6211, 0.0054)
  curve K2 (43.458, 17.2508) -> (4.57, 42.9423)
  curve K3 (4.57, 42.9423) -> (43.458, 17.2508)
  curve K4 (25.3428, 0.0031) -> (25.3428, 0.0031)
  curve K5 (-10.518, -15.9674) -> (25.3428, 0.0012)
  curve K6 (-15.238, 9.3651) -> (-15.2862, -9.1369)
  curve K7 (-15.2862, -9.1369) -> (-10.518, -15.9674)
  curve K8 (25.3428, 0.0031) -> (-9.3679, 17.0015)
  line L1 (25.3428, 0.0012) -> (25.3428, 0.0031)
  curve K9 (21.6211, 0.0054) -> (25.3428, 0.0012)
  curve K10 (-9.3679, 17.0015) -> (-15.238, 9.3651)
  curve K11 (21.6211, 0.0054) -> (25.3428, 0.0012)
  circle C1 centre (4, 0) radius 10
  circle C2 centre (1.0947, 39.3629) radius 1.5
  circle C3 centre (1.0947, -39.4803) radius 1.5
  circle C4 centre (4.0683, -0.0177) radius 24.5
  dimension "d245" diameter C1 = 20
extrude "Estrusione3" cut sketch "Schizzo45" profile of C1 to an object
sketch "Schizzo38" plane through (-0.0683, 0.0177, -180) normal (0, 0, 1) x axis (1, 0, 0)
  curve K1 (43.458, 17.2508) -> (4.57, 42.9423)
  curve K2 (4.57, 42.9423) -> (43.458, 17.2508)
  curve K3 (25.3428, 0.0031) -> (25.3428, 0.0031)
  circle C1 centre (4.426, 0.041) radius 23
  circle C2 centre (1.0947, 39.3629) radius 1.5
  circle C3 centre (1.0947, -39.4803) radius 1.5
  circle C4 centre (4, 0) radius 10
  circle C5 centre (4.0683, -0.0177) radius 24.5
fillet "Raccordo6" radius 15.5
fillet "Raccordo5" radius 2
delete_face "EliminaFaccia"
thread "Filettatura2" ThreadOffset 0 ThreadLength 3
offset_faces "FacceDiOffset3" distance -0.1
offset_faces "FacceDiOffset4" distance -0.1
work_plane "Piano di lavoro13" AlongDistance -7
sketch "Schizzo61" plane through (4.4245, -0.0371, -175) normal (0, 0, -1) x axis (1, 0, 0)
  arc A1 centre (-0.0668, -0.0139) radius 24.911 clockwise from (-13.1516, 21.1839) to (-16.1837, 18.9809)
  circle C1 centre (-0.0668, -0.0139) radius 25.2
  circle C2 centre (-0.0668, -0.0139) radius 35.2
  concentric A1 C1
  concentric C1 C2
  dimension "d260" diameter C1 = 50.4
  dimension "d261" distance C1 C2 = 10
extrude "Estrusione1" new body sketch "Schizzo61" profile of C1 C2 against normal blind 3
sketch "Schizzo62" plane through (0, 0, -172) normal (0, 0, 1) x axis (-1, 0, 0)
  curve K1 (-39.0425, 6.0232) -> (-36.8552, 7.0934)
  curve K2 (-39.0425, -5.9768) -> (-36.8646, -7.0503)
  line L1 (-4.3577, -35.1512) -> (-4.3577, 35.1977)
  curve K3 (30.3272, 6.0232) -> (28.1399, 7.0934)
  curve K4 (-36.6507, 7.021) -> (-37.0597, 7.1658)
  curve K5 (-39.0053, 6.2386) -> (-39.0798, 5.8078)
  curve K6 (27.9354, 7.021) -> (28.3443, 7.1658)
  curve K7 (30.2899, 6.2386) -> (30.3645, 5.8078)
  curve K8 (30.3272, -5.9768) -> (28.1493, -7.0503)
  curve K9 (-36.6321, -6.9684) -> (-37.0972, -7.1323)
  curve K10 (-39.0019, -6.2119) -> (-39.0832, -5.7416)
  curve K11 (27.9168, -6.9684) -> (28.3818, -7.1323)
  curve K12 (30.2865, -6.2119) -> (30.3679, -5.7416)
  line L2 (-39.0425, 6.0232) -> (-39.0425, -5.9768)
  line L3 (-39.0425, 0.0232) -> (-39.3577, 0.0232)
  line L4 (-4.3577, 0.0232) -> (-39.0425, 0.0232)
  circle C1 centre (-4.3577, 0.0232) radius 35.2
  circle C2 centre (-39.3577, 0.0232) radius 7.5
  circle C3 centre (-39.3577, 0.0232) radius 1.7
  circle C4 centre (30.6423, 0.0232) radius 7.5
  circle C5 centre (30.6423, 0.0232) radius 1.7
  circle C6 centre (-4.3577, 0.0232) radius 35.2
  circle C7 centre (-4.3577, 0.0232) radius 25.2
  circle C8 centre (-4.3577, 0.0232) radius 25.2
  point P5 (-36.8552, 7.0934)
  point P6 (-39.0425, 6.0232)
  point P7 (-36.8646, -7.0503)
  point P8 (-39.0425, -5.9768)
  point P12 (28.1399, 7.0934)
  point P11 (30.3272, 6.0232)
  point P13 (28.1493, -7.0503)
  point P15 (30.3272, -5.9768)
  point P16 (-37.0597, 7.1658)
  point P20 (28.3443, 7.1658)
  point P17 (-36.6507, 7.021)
  point P21 (27.9354, 7.021)
  point P18 (-39.0798, 5.8078)
  point P22 (30.3645, 5.8078)
  point P19 (-39.0053, 6.2386)
  point P23 (30.2899, 6.2386)
  point P24 (-37.0972, -7.1323)
  point P28 (28.3818, -7.1323)
  point P25 (-36.6321, -6.9684)
  point P29 (27.9168, -6.9684)
  point P26 (-39.0832, -5.7416)
  point P30 (30.3679, -5.7416)
  point P27 (-39.0019, -6.2119)
  point P31 (30.2865, -6.2119)
  point P4 (-39.3577, 0.0232)
  point P32 (-39.3577, 0.0232)
  point P33 (-39.0425, 0.0232)
  point P2 (-4.3577, 0.0232)
  point P34 (-4.3577, 0.0232)
  point P3 (-39.3577, 0.0232)
  concentric C2 C3
  coincident C2 P5
  coincident C1 P6
  coincident C2 P7
  coincident C1 P8
  tangent C1 K1
  tangent C2 K1
  tangent C2 K2
  tangent C1 K2
  vertical L1
  midpoint P5 K4
  midpoint P6 K5
  midpoint P7 K9
  midpoint P8 K10
  symmetric C2 L1 C4
  symmetric P5 L1 P12
  symmetric P6 L1 P11
  symmetric P7 L1 P13
  symmetric P8 L1 P15
  symmetric L1 P16 P20
  symmetric L1 P17 P21
  symmetric L1 P18 P22
  symmetric L1 P19 P23
  symmetric L1 P24 P28
  symmetric L1 P25 P29
  symmetric L1 P26 P30
  symmetric L1 P27 P31
  coincident P4 P32
  midpoint L2 P33
  coincident P2 P34
  perpendicular L1 L4
  perpendicular L2 L3
  symmetric C3 L1 C5
  midpoint L1 P34
  dimension "d264" diameter C2 = 15
  dimension "d265" diameter C3 = 3.4
  dimension "d271" distance P6 P8 = 12
  dimension "d272" diameter C1 = 70.4
  dimension "d280" distance P3 P34 = 35
extrude "Estrusione2" new body sketch "Schizzo62" profile of C1 C2 C3 K1 K2 K3 C4 K8 C5 C6 C7 C8 to an object
sketch "Schizzo73" plane through (0, 0, 0) normal (1, 0, 0) x axis (0, 0, -1)
  line L1 (-215.9221, -25) -> (215.9221, -25)
  line L2 (-215.9221, 25) -> (-215.9221, -25)
  line L3 (215.9221, 25) -> (-215.9221, 25)
  line L4 (215.9221, -25) -> (215.9221, 25)
  line L5 (-215.9221, 25) -> (215.9221, -25)
  line L6 (215.9221, 25) -> (-215.9221, -25)
  line L7 (175, -35.2232) -> (175, -7.4989)
  line L8 (172, -7.4989) -> (175, -7.4989)
  line L9 (172, -35.2232) -> (172, -7.4989)
  line L10 (175, -7.4989) -> (172, -7.4989)
  line L11 (175, 7.4525) -> (175, 35.1768)
  line L12 (172, 7.4525) -> (175, 7.4525)
  line L13 (172, 7.4525) -> (172, 35.1768)
  line L14 (175, 7.4525) -> (172, 7.4525)
  point P6 (0, 0)
  point P1 (0, 0)
  point P2 (215.9221, -25)
  point P5 (215.9221, 25)
  horizontal L1
  perpendicular L1 L2
  parallel L1 L3
  parallel L2 L4
  coincident L5 P6
  coincident L6 P6
  coincident P1 P6
  dimension "d325" distance P2 P5 = 50
sketch "Schizzo74" plane through (0, 0, -175) normal (0, 0, -1) x axis (1, 0, 0)
  curve K1 (28.1623, -0.0177) -> (-19.5597, 2.6308)
  curve K2 (-19.5597, 2.6308) -> (-19.6619, -0.221)
  curve K3 (-19.6619, -0.221) -> (28.1623, -0.0177)
  circle C1 centre (4.3577, 0.0232) radius 25.2
  circle C2 centre (-30.6423, 0.0232) radius 1.7
  circle C3 centre (39.3577, 0.0232) radius 1.7
  arc A1 centre (4.3577, 0.0232) radius 35.2 clockwise from (-30.0393, 7.4989) to (38.7547, 7.4989)
  arc A2 centre (-30.6423, 0.0232) radius 7.5 clockwise from (-30.0393, -7.4525) to (-30.0393, 7.4989)
  arc A3 centre (4.3577, 0.0232) radius 35.2 clockwise from (38.7547, -7.4525) to (-30.0393, -7.4525)
  arc A4 centre (39.3577, 0.0232) radius 7.5 clockwise from (38.7547, 7.4989) to (38.7547, -7.4525)
sketch "Schizzo63" plane through (0, 0, -175) normal (0, 0, -1) x axis (1, 0, 0)
  arc A1 centre (-30.6423, 0.0232) radius 7.5 clockwise from (-30.0393, -7.4525) to (-30.0393, 7.4989)
  arc A2 centre (39.3577, 0.0232) radius 7.5 clockwise from (38.7547, 7.4989) to (38.7547, -7.4525)
  circle C1 centre (39.3577, 0.0232) radius 3
  circle C2 centre (-30.6423, 0.0232) radius 1.7
  circle C3 centre (-30.6423, 0.0232) radius 3
  circle C4 centre (39.3577, 0.0232) radius 1.7
  arc A3 centre (4.3577, 0.0232) radius 35.2 clockwise from (-30.0393, 7.4989) to (38.7547, 7.4989)
  circle C5 centre (-30.6423, 0.0232) radius 1.7
  circle C6 centre (39.3577, 0.0232) radius 1.7
  circle C7 centre (4.3577, 0.0232) radius 25.2
  arc A4 centre (4.3577, 0.0232) radius 35.2 clockwise from (38.7547, -7.4525) to (-30.0393, -7.4525)
  concentric C1 C4
  concentric C2 C3
  dimension "d268" diameter C1 = 6
  dimension "d273" diameter C3 = 6 (= "d268")
extrude "Estrusione3" cut sketch "Schizzo63" profile of C4 C1 C2 C3 against normal blind 1.7
draft "Sformo1" Angle1 45 Angle2 0
draft "Sformo2" Angle1 45 Angle2 0
sketch "Schizzo64" plane through (0, 0, -175) normal (0, 0, -1) x axis (1, 0, 0)
  circle C1 centre (39.3577, 0.0232) radius 3
  circle C2 centre (-30.6423, 0.0232) radius 3
  arc A1 centre (-30.6423, 0.0232) radius 7.5 clockwise from (-30.0393, -7.4525) to (-30.0393, 7.4989)
  arc A2 centre (39.3577, 0.0232) radius 7.5 clockwise from (38.7547, 7.4989) to (38.7547, -7.4525)
  circle C3 centre (4.3577, 0.0232) radius 25.2
  circle C4 centre (4.3577, 0.0232) radius 26.8
  arc A3 centre (4.3577, 0.0232) radius 35.2 clockwise from (-30.0393, 7.4989) to (38.7547, 7.4989)
  circle C5 centre (4.3577, 0.0232) radius 25.2
  arc A4 centre (4.3577, 0.0232) radius 35.2 clockwise from (38.7547, -7.4525) to (-30.0393, -7.4525)
extrude "Estrusione4" add sketch "Schizzo64" profile of C3 C4 along normal blind 3.2
fillet "Raccordo1" radius 1.5
thread "Filettatura1" ThreadOffset 0 ThreadLength 3
offset_faces "FacceDiOffset1" distance 0.1
sketch "Schizzo65" plane through (0, 0, -172) normal (0, 0, 1) x axis (-1, 0, 0)
  line L1 (-100.3022, -52.7275) -> (100.3022, -52.7275)
  line L2 (-100.3022, 52.7275) -> (-100.3022, -52.7275)
  line L3 (100.3022, 52.7275) -> (-100.3022, 52.7275)
  line L4 (100.3022, -52.7275) -> (100.3022, 52.7275)
  line L5 (-100.3022, 52.7275) -> (100.3022, -52.7275)
  line L6 (100.3022, 52.7275) -> (-100.3022, -52.7275)
  arc A1 centre (30.6423, 0.0232) radius 7.5 clockwise from (30.0393, 7.4989) to (30.0393, -7.4525)
  arc A2 centre (-39.3577, 0.0232) radius 7.5 clockwise from (-38.7547, -7.4525) to (-38.7547, 7.4989)
  arc A3 centre (-4.3577, 0.0232) radius 35.2 clockwise from (-38.7547, 7.4989) to (30.0393, 7.4989)
  circle C1 centre (-4.3577, 0.0232) radius 25.2
  circle C2 centre (-39.3577, 0.0232) radius 1.7
  circle C3 centre (30.6423, 0.0232) radius 1.7
  arc A4 centre (-4.3577, 0.0232) radius 35.2 clockwise from (30.0393, -7.4525) to (-38.7547, -7.4525)
  point P13 (0, 0)
  point P1 (0, 0)
  horizontal L1
  perpendicular L1 L2
  parallel L1 L3
  parallel L2 L4
  coincident L5 P13
  coincident L6 P13
  coincident P1 P13
place_component sketch "Schizzo65"
extrude "Estrusione1" new body sketch "Schizzo65" profile of A1 A2 L1 L2 L3 L4 along normal blind 4
sketch "Schizzo66" plane through (0, 0, -168) normal (0, 0, 1) x axis (-1, 0, 0)
  line L1 (-100.3022, 52.7275) -> (100.3022, 52.7275)
  line L2 (-100.3022, -52.7275) -> (-100.3022, 52.7275)
  line L3 (100.3022, -52.7275) -> (-100.3022, -52.7275)
  line L4 (100.3022, 52.7275) -> (100.3022, -52.7275)
  arc A1 centre (30.6423, 0.0232) radius 7.5 clockwise from (30.0393, 7.4989) to (30.0393, -7.4525)
  arc A2 centre (-39.3577, 0.0232) radius 7.5 clockwise from (-38.7547, -7.4525) to (-38.7547, 7.4989)
  arc A3 centre (-4.3577, 0.0232) radius 35.2 clockwise from (-38.7547, 7.4989) to (30.0393, 7.4989)
  circle C1 centre (-39.3577, 0.0232) radius 1.7
  circle C2 centre (30.6423, 0.0232) radius 1.7
  circle C3 centre (-4.3577, 0.0232) radius 25.2
  arc A4 centre (-4.3577, 0.0232) radius 35.2 clockwise from (30.0393, -7.4525) to (-38.7547, -7.4525)
extrude "Estrusione1" new body sketch "Schizzo66" profile of A1 A2 A3 C1 C2 C3 A4 along normal blind 3
sketch "Schizzo67" plane through (0, 0, -165) normal (0, 0, 1) x axis (-1, 0, 0)
  arc A1 centre (-39.3577, 0.0232) radius 7.5 clockwise from (-38.7547, -7.4525) to (-38.7547, 7.4989)
  arc A2 centre (30.6423, 0.0232) radius 7.5 clockwise from (30.0393, 7.4989) to (30.0393, -7.4525)
  circle C1 centre (-39.3577, 0.0232) radius 1.5
  circle C2 centre (30.6423, 0.0232) radius 1.5
  arc A3 centre (-4.3577, 0.0232) radius 35.2 clockwise from (30.0393, -7.4525) to (-38.7547, -7.4525)
  arc A4 centre (-4.3577, 0.0232) radius 35.2 clockwise from (-38.7547, 7.4989) to (30.0393, 7.4989)
  circle C3 centre (-4.3577, 0.0232) radius 25.2
  circle C4 centre (30.6423, 0.0232) radius 1.7
  circle C5 centre (30.6423, 0.0232) radius 1.7
  circle C6 centre (-39.3577, 0.0232) radius 1.7
  circle C7 centre (-39.3577, 0.0232) radius 1.7
  point P8 (-39.3577, 0.0232)
  point P12 (-39.3577, 0.0232)
  point P9 (30.6423, 0.0232)
  point P11 (30.6423, 0.0232)
  coincident P8 P12
  coincident P9 P11
  dimension "d293" diameter C1 = 3
  dimension "d294" diameter C2 = 3
extrude "Estrusione2" add sketch "Schizzo67" profile of C1 C2 against normal blind 2
sketch "Schizzo68" plane through (0, 0, -165) normal (0, 0, 1) x axis (-1, 0, 0)
  arc A1 centre (-39.3577, 0.0232) radius 7.5 clockwise from (-38.7547, -7.4525) to (-38.7547, 7.4989)
  arc A2 centre (30.6423, 0.0232) radius 7.5 clockwise from (30.0393, 7.4989) to (30.0393, -7.4525)
  circle C1 centre (-39.3577, 0.0232) radius 1.9
  circle C2 centre (30.6423, 0.0232) radius 2.3
  arc A3 centre (-4.3577, 0.0232) radius 35.2 clockwise from (30.0393, -7.4525) to (-38.7547, -7.4525)
  arc A4 centre (-4.3577, 0.0232) radius 35.2 clockwise from (-38.7547, 7.4989) to (30.0393, 7.4989)
  circle C3 centre (-4.3577, 0.0232) radius 25.2
  circle C4 centre (30.6423, 0.0232) radius 5.3
  circle C5 centre (30.6423, 0.0232) radius 1.7
  circle C6 centre (30.6423, 0.0232) radius 1.7
  circle C7 centre (-39.3577, 0.0232) radius 1.7
  circle C8 centre (-39.3577, 0.0232) radius 1.7
  circle C9 centre (-39.3577, 0.0232) radius 2.3
  circle C10 centre (-39.3577, 0.0232) radius 5.3
  point P8 (-39.3577, 0.0232)
  point P13 (-39.3577, 0.0232)
  point P9 (30.6423, 0.0232)
  point P12 (30.6423, 0.0232)
  coincident P8 P13
  coincident P9 P12
  concentric C7 C9
  dimension "d297" diameter C1 = 3.8
  dimension "d298" diameter C2 = 4.6
  dimension "d314" = 3 (= "d317")
  dimension "d315" diameter C5 = 3.4
  dimension "d316" diameter C9 = 4.6
  dimension "d317" = 3
extrude "Estrusione3" add sketch "Schizzo68" profile of C2 C4 C9 C10 along normal blind 2.7
extrude "Estrusione5" cut of existing geometry blind -3.5
sketch "Schizzo71" plane through (0, 0, -162.3) normal (0, 0, 1) x axis (-1, 0, 0)
  circle C1 centre (30.6423, 0.0232) radius 2.3
  circle C2 centre (30.6423, 0.0232) radius 5.3
  circle C3 centre (-39.3577, 0.0232) radius 2.3
  circle C4 centre (-39.3577, 0.0232) radius 5.3
extrude "Estrusione6" add sketch "Schizzo71" along normal blind 3
chamfer "Smusso1" distance 1 distance 2.5
sketch "Schizzo69" plane through (0, 0, -161) normal (0, 0, 1) x axis (-1, 0, 0)
  circle C1 centre (-37.3577, 0.0232) radius 1.5
  circle C2 centre (-37.3577, 0.0232) radius 1.9
  circle C3 centre (28.6423, 0.0232) radius 1.9
  circle C4 centre (-37.3577, 0.0232) radius 1.9
extrude "Estrusione4" add sketch "Schizzo69" along normal blind 0.8
fillet "Raccordo1" radius 1
combine "Combina1"
fillet "Raccordo2"
chamfer "Smusso6" distance 2
sketch "Schizzo72" plane through (0, 0, -175) normal (0, 0, -1) x axis (1, 0, 0)
  curve K1 (28.1623, -0.0177) -> (-19.5597, 2.6308)
  curve K2 (-19.5597, 2.6308) -> (-19.6619, -0.221)
  curve K3 (-19.6619, -0.221) -> (28.1623, -0.0177)
sketch "Schizzo75" plane through (0, 0, -182) normal (0, 0, -1) x axis (1, 0, 0)
  curve K1 (43.3897, -17.2685) -> (4.5017, -42.9601)
  curve K2 (4.5017, -42.9601) -> (43.3897, -17.2685)
  circle C1 centre (3.9317, -0.0177) radius 10
  circle C2 centre (1.0264, -39.3806) radius 1.5
  circle C3 centre (1.0264, 39.4626) radius 1.5
  circle C4 centre (4, 0) radius 24.5
  circle C5 centre (4, 0) radius 24.5
sketch "Schizzo76" plane through (0, 0, -175) normal (0, 0, -1) x axis (1, 0, 0)
  circle C1 centre (39.3577, 0.0232) radius 3
  circle C2 centre (-30.6423, 0.0232) radius 3
  circle C3 centre (4.3577, 0.0232) radius 25.2
  arc A1 centre (4.3577, 0.0232) radius 35.2 clockwise from (-30.0393, 7.4989) to (38.7547, 7.4989)
  arc A2 centre (-30.6423, 0.0232) radius 7.5 clockwise from (-30.0393, -7.4525) to (-30.0393, 7.4989)
  arc A3 centre (4.3577, 0.0232) radius 35.2 clockwise from (38.7547, -7.4525) to (-30.0393, -7.4525)
  arc A4 centre (39.3577, 0.0232) radius 7.5 clockwise from (38.7547, 7.4989) to (38.7547, -7.4525)
  circle C4 centre (4.3577, 0.0232) radius 28.2
  dimension "d329" = 3
extrude "Estrusione5" add sketch "Schizzo76" profile of C3 C4 along normal blind 5
sketch "Schizzo77" plane through (0, 0, 0) normal (1, 0, 0) x axis (0, 0, -1)
  line L1 (172, -0.0232) -> (180, -0.0232)
  line L2 (175, -0.0232) -> (180, -0.0232)
  line L3 (175, -5.0232) -> (175, -0.0232)
  point P2 (180, -0.0232)
  point P3 (180, -0.0232)
  point P5 (180, -0.0232)
  point P6 (175, -0.0232)
  point P7 (175, -5.0232)
  coincident P2 P3
  horizontal L1
  coincident P2 P5
  parallel L1 L2
  perpendicular L2 L3
  dimension "d332" distance P5 P6 = 5
  dimension "d333" distance P6 P7 = 5
sketch "Schizzo78" plane through (0, 0, -180) normal (0, 0, -1) x axis (1, 0, 0)
  line L1 (35.5401, 4.0232) -> (-26.8247, 4.0232)
  line L2 (35.5401, -3.9768) -> (35.5401, 4.0232)
  line L3 (-26.8247, -3.9768) -> (35.5401, -3.9768)
  line L4 (-26.8247, 4.0232) -> (-26.8247, -3.9768)
  line L5 (35.5401, -3.9768) -> (-26.8247, 4.0232)
  line L6 (-26.8247, -3.9768) -> (35.5401, 4.0232)
  line L7 (8.3577, 31.0557) -> (0.3577, 31.0557)
  line L8 (8.3577, -31.0093) -> (8.3577, 31.0557)
  line L9 (0.3577, -31.0093) -> (8.3577, -31.0093)
  line L10 (0.3577, 31.0557) -> (0.3577, -31.0093)
  line L11 (8.3577, -31.0093) -> (0.3577, 31.0557)
  line L12 (0.3577, -31.0093) -> (8.3577, 31.0557)
  circle C1 centre (4.3577, 0.0232) radius 25.2
  circle C2 centre (4.3577, 0.0232) radius 28.2
  point P7 (4.3577, 0.0232)
  point P2 (4.3577, 0.0232)
  point P12 (4.3577, 0.0232)
  point P8 (0.3577, 31.0557)
  point P9 (8.3577, 31.0557)
  point P3 (-26.8247, 4.0232)
  point P6 (-26.8247, -3.9768)
  horizontal L1
  perpendicular L1 L2
  parallel L1 L3
  parallel L2 L4
  coincident L5 P7
  coincident L6 P7
  coincident P2 P7
  horizontal L7
  perpendicular L7 L8
  parallel L7 L9
  parallel L8 L10
  coincident L11 P12
  coincident L12 P12
  coincident P7 P12
  dimension "d334" distance P8 P9 = 8
  dimension "d335" distance P3 P6 = 8
extrude "Estrusione6" cut sketch "Schizzo78" profile of C1 C2 L1 L3 L8 L10 against normal blind 5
